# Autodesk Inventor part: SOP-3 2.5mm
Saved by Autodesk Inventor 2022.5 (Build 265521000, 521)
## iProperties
Created: 2024-12
Part Number: SOP-3 2.5mm
Material: Generic
Document SubType Name: Modeling
Designer: AdminForWorker
Density: 1 g/cm^3
Appearance: Default
Title: SOP-3 2.5mm v1
Author: AdminForWorker
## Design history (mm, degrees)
feature "Body1" [lead]
feature "lead2"
feature "lead1"
feature "lead3"
body "Solid1"
body "Solid2"
body "Solid3"
body "Solid4"
